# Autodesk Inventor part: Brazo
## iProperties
Shininess: 64.0
Length Units: 11272
Angle Units: 11279
Time Units: 11290
Mass Units: 11286
Length Display Precision: 3
Angle Display Precision: 2
Compacted: True
Part Number: Brazo
Document SubType Name: Modeling
Created: 2005-06
Designer: alek
Manufacturer: Standard
Standards Organization: Custom
Density: 0.0
Volumn: 0.0
Area: 0.0
PropertySet Name: Model Information
Control State: 0
Master: False
Checked Out: False
Author: alek
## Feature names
1. Extrusion1
2. Extrusion2
3. Hole1
4. Hole2
5. Extrusion3
